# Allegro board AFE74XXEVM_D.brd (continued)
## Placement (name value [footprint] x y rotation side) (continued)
T3  NCR2-113+  [BALUN_6_NCR2]  35.74 62.33 270 bottom
T4  TCM2-672X+  [TFMR_6_160X150_50]  42.93 31.54 255 top
T5  TC1-1-43X+  [TFMR_5_150X150_50]  43.86 37.47 255 top
T6  TCM2-672X+  [TFMR_6_160X150_50]  48.45 30.06 255 top
T7  TC1-1-43X+  [TFMR_5_150X150_50]  49.38 35.99 255 top
T8  TCM2-672X+  [TFMR_6_160X150_50]  63.1 30.3 285 top
T9  TC1-1-43X+  [TFMR_5_150X150_50]  60.94 35.9 285 top
T10  TCM2-672X+  [TFMR_6_160X150_50]  68.62 31.78 285 top
T11  TC1-1-43X+  [TFMR_5_150X150_50]  66.46 37.38 285 top
T12  TCM2-672X+  [TFMR_6_160X150_50]  41.88 95.29 105 top
T13  TC1-1-43X+  [TFMR_5_150X150_50]  44.04 89.69 105 top
T14  TCM2-672X+  [TFMR_6_160X150_50]  47.4 96.77 105 top
T15  TC1-1-43X+  [TFMR_5_150X150_50]  49.56 91.17 105 top
T16  TCM2-672X+  [TFMR_6_160X150_50]  62.29 97 75 top
T17  TC1-1-43X+  [TFMR_5_150X150_50]  61.36 91.07 75 top
T18  TCM2-672X+  [TFMR_6_160X150_50]  67.81 95.52 75 top
T19  TC1-1-43X+  [TFMR_5_150X150_50]  66.88 89.59 75 top
T20  TCM3-452X-1+  [TFMR_6_160X150_50]  33.67 45.76 210 top
T21  TCM3-452X-1+  [TFMR_6_160X150_50]  29.79 57.1 180 top
T22  TCM3-452X-1+  [TFMR_6_160X150_50]  33.75 81.47 150 top
T23  TCM3-452X-1+  [TFMR_6_160X150_50]  29.79 69.81 180 top
T24  TC1-1-13M+  [TFMR_5_150X150_50]  99.16 104.39 270 bottom
TP1  Testloop_Red  [TESTPOINT_62DIA]  185.8 3.07 0 top
TP2  Testloop_Black  [TESTPOINT_62DIA]  180.82 3.02 0 top
TP3  TP_THVT_060_RND-WHT  [TP_THVT_060_RND]  214.91 32 0 top
TP4  TP_THVT_060_RND-WHT  [TP_THVT_060_RND]  201.24 94.95 0 top
TP5  TP_THVT_060_RND-WHT  [TP_THVT_060_RND]  198.96 88.29 0 top
U1  AFE76XX  [BGA_20X20_400_P8MM]  57.15 63.5 180 top
U2  NB7V33M  [QFN_16_124X124_PWRPAD]  92.15 104.52 0 bottom
U3  LMK04828  [QFN_64_360X360_0P50MM_PWRPAD]  102.34 90.86 90 bottom
U4  LP5907-3.3  [DBV5]  195.08 90.72 0 top
U5  FT4232H  [LQFP_64_402X402_20]  185.06 107.75 180 top
U6  TXS0108E  [QFN_20_183X144_RGY]  182.65 118.29 270 top
U7  TXS0108E  [QFN_20_183X144_RGY]  174.9 109.47 270 top
U8  93LC46B-I/MS  [MSOP_8_118X118_26]  187.5 96.9 270 top
U9  TXS0108E  [QFN_20_183X144_RGY]  174.78 102.49 270 top
U10  TXS0104E  [TSSOP14]  180.87 95.78 270 top
U11  TPS7A4700  [QFN20_RGW_P65PITCH]  178.1 30.02 270 top
U12  TPS2400  [DBV5]  185.72 17.5 0 top
U13  TPS62160  [SON_DSG_8]  92.2 8.69 0 top
U15  INA193  [DBV5]  82.04 13.49 0 top
U16  TPS56121  [SON_DQP_22_PWRPAD]  153.21 9.83 270 top
U17  INA195  [DBV5]  142.77 12.85 180 top
U18  TPS62480  [QFN16_RNC]  165.71 13.16 90 top
U19  INA193  [DBV5]  116.54 16.28 90 bottom
U20  TPS7A8300  [QFN20_RGW_P65PITCH]  116.74 10.74 0 top
U21  INA193  [DBV5]  89.23 21.59 0 bottom
U22  TPS7A8300  [QFN20_RGW_P65PITCH]  83.39 21.34 270 top
U23  TPS7A8300  [QFN20_RGW_P65PITCH]  119.08 23.77 0 top
U24  INA193  [DBV5]  119.13 29.31 90 bottom
U25  TPS7A8300  [QFN20_RGW_P65PITCH]  128.12 7.67 0 top
U26  INA193  [DBV5]  127.97 13.23 90 bottom
U27  TPS7A8300  [QFN20_RGW_P65PITCH]  147.96 27.76 0 top
U28  INA193  [DBV5]  147.75 33.2 90 bottom
U29  TPS7A8300  [QFN20_RGW_P65PITCH]  130.4 23.67 0 top
U30  INA193  [DBV5]  130.12 29.29 90 bottom
U31  24LC65  [SO_8_210X212_50]  191.47 22.07 90 top
U32  TPS7A4700  [QFN20_RGW_P65PITCH]  166.42 30.28 270 top
U33  TXS0104E  [TSSOP14]  175.01 94.23 90 top
Y1  122.88MHz  [VCXO_6_CUSTOM]  108.38 110.47 225 bottom
Y2  12MHz w/ 10pF  [XTAL_4_SM_130X102]  186.79 106.73 90 bottom

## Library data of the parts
C1 C4 C7 C132 C137 C148 C155 C228 C229 C253 C254 C256 C257 C278 C281 C288 C305 C306 C309 C313 C315 C317 C318 C358 C362 C377 C380 C390 C391 C399 C401 C408 C412 C419 C420 C434 C436 C440 C471 C479 C487 C495 = CAP NP_1: tolerance: 10%
C2 C3 C6 C9-C40 C64 C65 C80 C103 C106 C109 C113 C116 C119 C125 C126 C271 C282 C429-C431 C459-C461 C464 = CAP0402_0: tolerance: 10%
C41-C48 = CAP_0402_0.001uF_H
C49 C135 C139 C156 C161 C227 C231 C233-C239 C476 C484 C492 C500 = CAP_0402_0.01uF_H: tolerance: 10%
C50 C51 C61 C66 C67 C76 C78 C81 C82 C91 C93 C95-C97 C99 C101 C104 C107 C111 C114 C117 C122 C326 C332 C336 C349 C351 C357 C360 C364 C366 C368 C370 C375 C379 C383 C388 C395 C403 C411 C416 = CAP0201_0: tolerance: 20%
C52-C60 C63 C68-C75 C83-C90 C120 C121 C124 C183 C196 C203 C215 C353 C354 C372 C373 C385 C386 C396 C397 C405 C406 C414 C415 C441 C442 C457 C458 C463 = CAP0402_0: tolerance: 20%
C62 C77 C79 C92 C94 C98 C100 C102 C105 C108 C110 C112 C115 C118 C123 C311 C312 C361 C381 C392 C400 C409 C421 C433 C435 C462 C465 = CAP0201_0: tolerance: 10%
C127 C133 C140 C141 C149 C150 C157 C158 C469 C470 C477 C478 C485 C486 C493 C494 = CAP_0402_0.01uF_H
C129 C130 C142 C143 C151 C152 C159 C160 C472 C473 C480 C481 C488 C489 C496 C497 = CAP_0603_0.1uF_H
C131 C136 C144-C147 C153 C154 C474 C475 C482 C483 C490 C491 C498 C499 = CAP_0603_0.1uF_H: tolerance: .1pF
C184 C186-C189 C191 C194 C195 C198-C202 C205-C208 C210 C213 C214 C217-C221 C224 C240 C241 C247 C249 C250 C258-C267 C269 C270 C273-C277 C279 C284-C286 C292-C295 C297 C299 C300 C307 C308 C327 C329 C423-C428 C438 C439 C443 C444 C501 = CAPACITOR_NP_1: tolerance: 10%
C185 C197 C204 C216 = CAPACITOR_NP_1: tolerance: .05pF
C190 C192 C193 C209 C211 C212 = CAP_0603_0.1uF
C222 C223 C225 C245 C252 C280 C301 C314 C316 C321 C328 C341 C432 = CAP NP_0: tolerance: 10%
C226 = CAP NP_0: tolerance: 5%
C230 = CAP_0402_0.1uF: tolerance: 10%
C242 C244 C251 = CAP_0402_0.1uF_H: tolerance: 10%
C243 = CAP_0603_100pF_H
C246 C338 C340 C342 C347 = CAP_0402_2200pF_H
C248 = CAP_0402_10pF_H
C255 = CAPACITOR_NP_1: tolerance: 1%
C268 = CAP NP_2: tolerance: 20%
C272 C283 = CAP NP_0: tolerance: 20%
C287 C289 C330 C337 C447-C450 = CAP_1206
C290 C291 = CAP NP: tolerance: 10%
C296 C298 = CAP NP: tolerance: 5%
C302 C322 C323 C335 C343-C346 C445 C446 C468 = CAP_1210_22uF
C303 C304 C333 C334 C466 C467 = CAP POL
C310 C437 = CAP0603: tolerance: 10%
C325 C331 C348 C350 C352 C355 C356 C359 C363 C365 C367 C369 C371 C374 C376 C378 C382 C384 C387 C389 C393 C394 C398 C402 C404 C407 C410 C413 C417 C418 C451-C456 = CAP NP_1: tolerance: 20%
C422 = CAP NP_1
D1-D10 D14 = LED
D11 = LED_AMBER_1206
D12 = LED_GREEN_1206
D13 = DIODE SCHOTTKY
F1 = FUSE_0
FB1-FB11 = FERRITE_BEAD_0402_H
FB12 FB14 FB15 = FERRITE_BEAD
FB13 FB17 FB18 FB21-FB37 = BEAD_NFM31P
FB19 FB20 FB38 = FILTER_YFF31HC
HS1 = HEATSINK_1
J1 J3 J22-J25 = TMP_122841
J2 J4-J6 J27-J31 = SMP_PLUG_SMT
J7 = HEADER_3x18_100
J8 = HEADER_2x2_100
J9 = HEADER_3x21_100
J10 = HEADER_3x5_100
J11 = HEADER_2x5_100
J12 = HEADER_2x8_100
J13 = HEADER_3x8_100
J14-J21 J26 = SMA-END_PLUG_ROUND
J32 = CON_SMVT_40X10_ASP-134487-01
J33 = USB_MINI_AB_MNE20-5G5P10
J35 = CONN JACK PWR
J36 = HEADER_3x4_100
J37 = HEADER_1x4_100
J38 = HEADER 2/SM
JP1-JP8 = HDR_2x1_100
JP9 = HEADER 3
L1-L18 L27 L28 L33-L36 L41-L65 = CHOKE
L29 L31 L37 L39 = IND_0603_120nH_H
MT1-MT6 = MOUNTING_HOLE
PP1-PP32 = PROBE_POINT_0
Q1-Q23 Q26 Q27 = MMBT2222A
Q24 = CSD18532Q5B
Q25 = MOSFET_SiA517DJ
R1 R3 R4 R8 R10 R11 R14 R21 R40-R47 R50 R52 R54 R72 R74 R76 R93 R94 R96 R115 R118 R119 R202 R204-R206 R288 R330-R332 R335-R337 R340-R342 R345-R347 = Res_0603_Zero_H
R2 R7 R9 R166 = Res_0402_49.9
R5 R15 R16 R48 R58 R73 R77 R95 R97 R114 R116 R156 R158 R169 R172 R189 R191 R295 R296 R333 R334 R338 R339 R343 R344 R348 R349 = Res_0402_Zero_H_DNI
R6 R157 R302-R305 R309-R320 R322 R323 = Res_0402_49.9: tolerance: 1%
R12 R13 R32-R39 R138 R139 R142 R143 R146 R147 R150 R151 R196 R208-R210 R222-R224 R229 R234 R238 R246 R249 R251-R255 R257-R263 R265-R268 R270-R274 R276-R280 R282-R285 R297-R300 R321 = R: tolerance: 5%
R17 R20 R22-R25 R27-R29 R215-R219 R247 R248 R329 = R_0: tolerance: 1%
R18 R19 R26 R201 R203 R207 R214 R235-R237 R239 R240 R243-R245 R286 R287 R301 R308 R327 RS1-RS8 = R: tolerance: 1%
R30 R221 R306 R307 = Res_0402_1k
R31 R153 R160 R228 R232 R233 R241 R250 R256 R264 R269 R275 R281 R324-R326 R328 = R_1: tolerance: 1%
R136 R140 R144 R148 R211 R212 = Res_0402_10_H
R137 R141 R145 R149 R178 R184 = Res_0402_100_H
R152 = Res_0402_24.9
R154 R155 R162 R163 R167 R168 R173 R174 R176 R177 R182 R183 R187 R188 R190 R192-R194 R289-R294 = Res_0402_249
R159 = Res_0603_Zero_DNI
R161 = Res_0402_18
R164 R165 = Res_0402_270
R170 R171 R175 R179-R181 R185 R186 = RESISTOR_0: tolerance: 1%
R195 R197-R200 = RESISTOR_0
R213 R220 = RESISTOR
SHIELD1-SHIELD4 = 4T4R_TX_SHIELD
SHIELD5-SHIELD8 = 4T4R_RX_SHIELD
SJP1 = SMD_JUMPER_1x3
SW1 = SW PUSHBUTTON
T1 = TFMR_6_TCM2-43X+
T2 T3 = BALUN_NCR2-113+
T4 T6 T8 T10 T12 T14 T16 T18 = BALUN_TCM2-672X+
T5 T7 T9 T11 T13 T15 T17 T19 = BALUN_TC1-1-43X+
T20-T23 = TFMR_6_TCM3-452X+
T24 = TFMR_5_TC1-1-13MA+
TP1 TP2 = TESTLOOP_BLACK
TP3-TP5 = TP_THVT_060_RND-WHT
U1 = AFE768x
U2 = NB7V33M
U3 = LMK04828
U4 = LP5907
U5 = FT4232H_2
U6 U7 U9 = TXS0108E
U8 = EEPROM
U10 U33 = TXS0104E: Tolerance: ***; User Part Number: ***
U11 U32 = TPS7A4700
U12 = TPS2400
U13 = TPS6217x_SON8
U15 U17 U19 U21 U24 U26 U28 U30 = INA138
U16 = TPS56121
U18 = TPS62480/VQFN16
U20 U22 U23 U25 U27 U29 = TPS7A8300
U31 = 24LC65
Y1 = OSC_SM_6_TCO-2100-SERIES_2
Y2 = CRYSTAL1-4/SM

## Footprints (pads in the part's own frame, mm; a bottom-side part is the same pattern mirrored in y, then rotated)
4T4R_RX_SHIELD
  round 1.676 hole 1.168: MT1(0,-4.064) MT2(0,-9.144) MT3(13.335,-2.921) MT4(13.335,-11.811)
4T4R_TX_SHIELD
  round 1.676 hole 1.168: MT1(1.524,-8.89) MT2(4.318,0) MT3(8.128,-8.89)
0201
  rect 0.305x0.305 smd: 1(-0.305,0) 2(0.305,0)
0204
  rect 0.254x1.016 smd: 1(-0.254,0) 2(0.254,0)
0306
  rect 0.508x1.778 smd: 1(-0.483,0) 2(0.483,0)
0402
  rect 0.508x0.635 smd: 1(-0.508,0) 2(0.508,0)
0508
  rect 0.559x2.007 smd: 1(-0.593,0) 2(0.593,0)
0603
  rect 0.762x0.787 smd: 1(-0.787,0) 2(0.787,0)
0805
  rect 1.016x1.27 smd: 1(-1.016,0) 2(1.016,0)
01005
  rect 0.152x0.203 smd: 1(-0.18,0) 2(0.18,0)
1206
  rect 1.321x1.6 smd: 1(-1.524,0) 2(1.524,0)
1206_BEAD_NFM31P
  rect 1.016x1.575 smd: 1(-1.778,0) 3(1.778,0)
  rect 1.321x2.032 smd: 2(0,0)
1210
  rect 0.965x2.489 smd: 1(-1.372,0) 2(1.372,0)
2512
  rect 1.016x3.175 smd: 1(-3.1,0) 2(3.1,0)
7343
  rect 2.388x2.642 smd: 1(-3.404,0) 2(3.404,0)
BALUN_6_NCR2
  rect 0.356x0.762 smd: 1(-0.71,0.89) 2(0,0.89) 3(0.71,0.89) 4(0.71,-0.89) 5(0,-0.89) 6(-0.71,-0.89)
BGA_20X20_400_P8MM
  round 0.406 smd: A1(-7.6,7.6) A2(-6.8,7.6) A3(-6,7.6) A4(-5.2,7.6) A5(-4.4,7.6) A6(-3.6,7.6) A7(-2.8,7.6) A8(-2,7.6) A9(-1.2,7.6) A10(-0.4,7.6) A11(0.4,7.6) A12(1.2,7.6) A13(2,7.6) A14(2.8,7.6) A15(3.6,7.6) A16(4.4,7.6) A17(5.2,7.6) A18(6,7.6) A19(6.8,7.6) A20(7.6,7.6) B1(-7.6,6.8) B2(-6.8,6.8) B3(-6,6.8) B4(-5.2,6.8) B5(-4.4,6.8) B6(-3.6,6.8) B7(-2.8,6.8) B8(-2,6.8) B9(-1.2,6.8) B10(-0.4,6.8) B11(0.4,6.8) B12(1.2,6.8) B13(2,6.8) B14(2.8,6.8) B15(3.6,6.8) B16(4.4,6.8) B17(5.2,6.8) B18(6,6.8) B19(6.8,6.8) B20(7.6,6.8) C1(-7.6,6) C2(-6.8,6) C3(-6,6) C4(-5.2,6) C5(-4.4,6) C6(-3.6,6) C7(-2.8,6) C8(-2,6) C9(-1.2,6) C10(-0.4,6) C11(0.4,6) C12(1.2,6) C13(2,6) C14(2.8,6) C15(3.6,6) C16(4.4,6) C17(5.2,6) C18(6,6) C19(6.8,6) C20(7.6,6) D1(-7.6,5.2) D2(-6.8,5.2) D3(-6,5.2) D4(-5.2,5.2) D5(-4.4,5.2) D6(-3.6,5.2) D7(-2.8,5.2) D8(-2,5.2) D9(-1.2,5.2) D10(-0.4,5.2) D11(0.4,5.2) D12(1.2,5.2) D13(2,5.2) D14(2.8,5.2) D15(3.6,5.2) D16(4.4,5.2) D17(5.2,5.2) D18(6,5.2) D19(6.8,5.2) D20(7.6,5.2) E1(-7.6,4.4) E2(-6.8,4.4) E3(-6,4.4) E4(-5.2,4.4) E5(-4.4,4.4) E6(-3.6,4.4) E7(-2.8,4.4) E8(-2,4.4) E9(-1.2,4.4) E10(-0.4,4.4) E11(0.4,4.4) E12(1.2,4.4) E13(2,4.4) E14(2.8,4.4) E15(3.6,4.4) E16(4.4,4.4) E17(5.2,4.4) E18(6,4.4) E19(6.8,4.4) E20(7.6,4.4) F1(-7.6,3.6) F2(-6.8,3.6) F3(-6,3.6) F4(-5.2,3.6) F5(-4.4,3.6) F6(-3.6,3.6) F7(-2.8,3.6) F8(-2,3.6) F9(-1.2,3.6) F10(-0.4,3.6) F11(0.4,3.6) F12(1.2,3.6) F13(2,3.6) F14(2.8,3.6) F15(3.6,3.6) F16(4.4,3.6) F17(5.2,3.6) F18(6,3.6) F19(6.8,3.6) F20(7.6,3.6) G1(-7.6,2.8) G2(-6.8,2.8) G3(-6,2.8) G4(-5.2,2.8) G5(-4.4,2.8) G6(-3.6,2.8) G7(-2.8,2.8) G8(-2,2.8) G9(-1.2,2.8) G10(-0.4,2.8) G11(0.4,2.8) G12(1.2,2.8) G13(2,2.8) G14(2.8,2.8) G15(3.6,2.8) G16(4.4,2.8) G17(5.2,2.8) G18(6,2.8) G19(6.8,2.8) G20(7.6,2.8) H1(-7.6,2) H2(-6.8,2) H3(-6,2) H4(-5.2,2) H5(-4.4,2) H6(-3.6,2) H7(-2.8,2) H8(-2,2) H9(-1.2,2) H10(-0.4,2) H11(0.4,2) H12(1.2,2) H13(2,2) H14(2.8,2) H15(3.6,2) H16(4.4,2) H17(5.2,2) H18(6,2) H19(6.8,2) H20(7.6,2) J1(-7.6,1.2) J2(-6.8,1.2) J3(-6,1.2) J4(-5.2,1.2) J5(-4.4,1.2) J6(-3.6,1.2) J7(-2.8,1.2) J8(-2,1.2) J9(-1.2,1.2) J10(-0.4,1.2) J11(0.4,1.2) J12(1.2,1.2) J13(2,1.2) J14(2.8,1.2) J15(3.6,1.2) J16(4.4,1.2) J17(5.2,1.2) J18(6,1.2) J19(6.8,1.2) J20(7.6,1.2) K1(-7.6,0.4) K2(-6.8,0.4) K3(-6,0.4) K4(-5.2,0.4) K5(-4.4,0.4) K6(-3.6,0.4) K7(-2.8,0.4) K8(-2,0.4) K9(-1.2,0.4) K10(-0.4,0.4) K11(0.4,0.4) K12(1.2,0.4) K13(2,0.4) K14(2.8,0.4) K15(3.6,0.4) K16(4.4,0.4) K17(5.2,0.4) K18(6,0.4) K19(6.8,0.4) K20(7.6,0.4) L1(-7.6,-0.4) L2(-6.8,-0.4) L3(-6,-0.4) L4(-5.2,-0.4) L5(-4.4,-0.4) L6(-3.6,-0.4) L7(-2.8,-0.4) L8(-2,-0.4) L9(-1.2,-0.4) L10(-0.4,-0.4) L11(0.4,-0.4) L12(1.2,-0.4) L13(2,-0.4) L14(2.8,-0.4) L15(3.6,-0.4) L16(4.4,-0.4) L17(5.2,-0.4) L18(6,-0.4) L19(6.8,-0.4) L20(7.6,-0.4) M1(-7.6,-1.2) M2(-6.8,-1.2) M3(-6,-1.2) M4(-5.2,-1.2) M5(-4.4,-1.2) M6(-3.6,-1.2) M7(-2.8,-1.2) M8(-2,-1.2) M9(-1.2,-1.2) M10(-0.4,-1.2) M11(0.4,-1.2) M12(1.2,-1.2) M13(2,-1.2) M14(2.8,-1.2) M15(3.6,-1.2) M16(4.4,-1.2) M17(5.2,-1.2) M18(6,-1.2) M19(6.8,-1.2) M20(7.6,-1.2) N1(-7.6,-2) N2(-6.8,-2) N3(-6,-2) N4(-5.2,-2) N5(-4.4,-2) N6(-3.6,-2) N7(-2.8,-2) N8(-2,-2) N9(-1.2,-2) N10(-0.4,-2) N11(0.4,-2) N12(1.2,-2) N13(2,-2) N14(2.8,-2) N15(3.6,-2) N16(4.4,-2) N17(5.2,-2) N18(6,-2) N19(6.8,-2) N20(7.6,-2) P1(-7.6,-2.8) P2(-6.8,-2.8) P3(-6,-2.8) P4(-5.2,-2.8) P5(-4.4,-2.8) P6(-3.6,-2.8) P7(-2.8,-2.8) P8(-2,-2.8) P9(-1.2,-2.8) P10(-0.4,-2.8) P11(0.4,-2.8) P12(1.2,-2.8) P13(2,-2.8) P14(2.8,-2.8) P15(3.6,-2.8) P16(4.4,-2.8) P17(5.2,-2.8) P18(6,-2.8) P19(6.8,-2.8) P20(7.6,-2.8) R1(-7.6,-3.6) R2(-6.8,-3.6) R3(-6,-3.6) R4(-5.2,-3.6) R5(-4.4,-3.6) R6(-3.6,-3.6) R7(-2.8,-3.6) R8(-2,-3.6) R9(-1.2,-3.6) R10(-0.4,-3.6) R11(0.4,-3.6) R12(1.2,-3.6) R13(2,-3.6) R14(2.8,-3.6) R15(3.6,-3.6) R16(4.4,-3.6) R17(5.2,-3.6) R18(6,-3.6) R19(6.8,-3.6) R20(7.6,-3.6) T1(-7.6,-4.4) T2(-6.8,-4.4) T3(-6,-4.4) T4(-5.2,-4.4) T5(-4.4,-4.4) T6(-3.6,-4.4) T7(-2.8,-4.4) T8(-2,-4.4) T9(-1.2,-4.4) T10(-0.4,-4.4) T11(0.4,-4.4) T12(1.2,-4.4) T13(2,-4.4) T14(2.8,-4.4) T15(3.6,-4.4) T16(4.4,-4.4) T17(5.2,-4.4) T18(6,-4.4) T19(6.8,-4.4) T20(7.6,-4.4) U1(-7.6,-5.2) U2(-6.8,-5.2) U3(-6,-5.2) U4(-5.2,-5.2) U5(-4.4,-5.2) U6(-3.6,-5.2) U7(-2.8,-5.2) U8(-2,-5.2) U9(-1.2,-5.2) U10(-0.4,-5.2) U11(0.4,-5.2) U12(1.2,-5.2) U13(2,-5.2) U14(2.8,-5.2) U15(3.6,-5.2) U16(4.4,-5.2) U17(5.2,-5.2) U18(6,-5.2) U19(6.8,-5.2) U20(7.6,-5.2) V1(-7.6,-6) V2(-6.8,-6) V3(-6,-6) V4(-5.2,-6) V5(-4.4,-6) V6(-3.6,-6) V7(-2.8,-6) V8(-2,-6) V9(-1.2,-6) V10(-0.4,-6) V11(0.4,-6) V12(1.2,-6) V13(2,-6) V14(2.8,-6) V15(3.6,-6) V16(4.4,-6) V17(5.2,-6) V18(6,-6) V19(6.8,-6) V20(7.6,-6) W1(-7.6,-6.8) W2(-6.8,-6.8) W3(-6,-6.8) W4(-5.2,-6.8) W5(-4.4,-6.8) W6(-3.6,-6.8) W7(-2.8,-6.8) W8(-2,-6.8) W9(-1.2,-6.8) W10(-0.4,-6.8) W11(0.4,-6.8) W12(1.2,-6.8) W13(2,-6.8) W14(2.8,-6.8) W15(3.6,-6.8) W16(4.4,-6.8) W17(5.2,-6.8) W18(6,-6.8) W19(6.8,-6.8) W20(7.6,-6.8) Y1(-7.6,-7.6) Y2(-6.8,-7.6) Y3(-6,-7.6) Y4(-5.2,-7.6) Y5(-4.4,-7.6) Y6(-3.6,-7.6) Y7(-2.8,-7.6) Y8(-2,-7.6) Y9(-1.2,-7.6) Y10(-0.4,-7.6) Y11(0.4,-7.6) Y12(1.2,-7.6) Y13(2,-7.6) Y14(2.8,-7.6) Y15(3.6,-7.6) Y16(4.4,-7.6) Y17(5.2,-7.6) Y18(6,-7.6) Y19(6.8,-7.6) Y20(7.6,-7.6)
CON_RAPC722_JACK_THVT_3
  round 4.318 hole 3.556: 1(0,3.124)
  round 3.81 hole 3.048: 2(0,-3.124) 3(4.801,0.127)
CON_SMRT_USBMINI_AB_F_MOD
  round 0.025 hole 0.9 unplated: (1.4,2.2) (1.4,-2.2)
  rect 2.261x0.508 smd: 1(3.725,1.6) 2(3.725,0.8) 3(3.725,0) 4(3.725,-0.8) 5(3.725,-1.6)
  rect 3.988x2.057 smd: 6(-0.5,4.92) 9(-0.5,-4.93)
  rect 3.505x2.057 smd: 7(3.75,4.92) 8(3.75,-4.93)
CON_SMVT_40X10_SEAM_MTG
  round 3.81 hole 2.692: (-31.496,-2.007) (31.496,-2.007)
  round 1.27 hole 1.27 unplated: (-27.191,-3.048) (27.191,0)
  round 0.635 smd: A1(24.765,5.715) A2(23.495,5.715) A3(22.225,5.715) A4(20.955,5.715) A5(19.685,5.715) A6(18.415,5.715) A7(17.145,5.715) A8(15.875,5.715) A9(14.605,5.715) A10(13.335,5.715) A11(12.065,5.715) A12(10.795,5.715) A13(9.525,5.715) A14(8.255,5.715) A15(6.985,5.715) A16(5.715,5.715) A17(4.445,5.715) A18(3.175,5.715) A19(1.905,5.715) A20(0.635,5.715) A21(-0.635,5.715) A22(-1.905,5.715) A23(-3.175,5.715) A24(-4.445,5.715) A25(-5.715,5.715) A26(-6.985,5.715) A27(-8.255,5.715) A28(-9.525,5.715) A29(-10.795,5.715) A30(-12.065,5.715) A31(-13.335,5.715) A32(-14.605,5.715) A33(-15.875,5.715) A34(-17.145,5.715) A35(-18.415,5.715) A36(-19.685,5.715) A37(-20.955,5.715) A38(-22.225,5.715) A39(-23.495,5.715) A40(-24.765,5.715) B1(24.765,4.445) B2(23.495,4.445) B3(22.225,4.445) B4(20.955,4.445) B5(19.685,4.445) B6(18.415,4.445) B7(17.145,4.445) B8(15.875,4.445) B9(14.605,4.445) B10(13.335,4.445) B11(12.065,4.445) B12(10.795,4.445) B13(9.525,4.445) B14(8.255,4.445) B15(6.985,4.445) B16(5.715,4.445) B17(4.445,4.445) B18(3.175,4.445) B19(1.905,4.445) B20(0.635,4.445) B21(-0.635,4.445) B22(-1.905,4.445) B23(-3.175,4.445) B24(-4.445,4.445) B25(-5.715,4.445) B26(-6.985,4.445) B27(-8.255,4.445) B28(-9.525,4.445) B29(-10.795,4.445) B30(-12.065,4.445) B31(-13.335,4.445) B32(-14.605,4.445) B33(-15.875,4.445) B34(-17.145,4.445) B35(-18.415,4.445) B36(-19.685,4.445) B37(-20.955,4.445) B38(-22.225,4.445) B39(-23.495,4.445) B40(-24.765,4.445) C1(24.765,3.175) C2(23.495,3.175) C3(22.225,3.175) C4(20.955,3.175) C5(19.685,3.175) C6(18.415,3.175) C7(17.145,3.175) C8(15.875,3.175) C9(14.605,3.175) C10(13.335,3.175) C11(12.065,3.175) C12(10.795,3.175) C13(9.525,3.175) C14(8.255,3.175) C15(6.985,3.175) C16(5.715,3.175) C17(4.445,3.175) C18(3.175,3.175) C19(1.905,3.175) C20(0.635,3.175) C21(-0.635,3.175) C22(-1.905,3.175) C23(-3.175,3.175) C24(-4.445,3.175) C25(-5.715,3.175) C26(-6.985,3.175) C27(-8.255,3.175) C28(-9.525,3.175) C29(-10.795,3.175) C30(-12.065,3.175) C31(-13.335,3.175) C32(-14.605,3.175) C33(-15.875,3.175) C34(-17.145,3.175) C35(-18.415,3.175) C36(-19.685,3.175) C37(-20.955,3.175) C38(-22.225,3.175) C39(-23.495,3.175) C40(-24.765,3.175) D1(24.765,1.905) D2(23.495,1.905) D3(22.225,1.905) D4(20.955,1.905) D5(19.685,1.905) D6(18.415,1.905) D7(17.145,1.905) D8(15.875,1.905) D9(14.605,1.905) D10(13.335,1.905) D11(12.065,1.905) D12(10.795,1.905) D13(9.525,1.905) D14(8.255,1.905) D15(6.985,1.905) D16(5.715,1.905) D17(4.445,1.905) D18(3.175,1.905) D19(1.905,1.905) D20(0.635,1.905) D21(-0.635,1.905) D22(-1.905,1.905) D23(-3.175,1.905) D24(-4.445,1.905) D25(-5.715,1.905) D26(-6.985,1.905) D27(-8.255,1.905) D28(-9.525,1.905) D29(-10.795,1.905) D30(-12.065,1.905) D31(-13.335,1.905) D32(-14.605,1.905) D33(-15.875,1.905) D34(-17.145,1.905) D35(-18.415,1.905) D36(-19.685,1.905) D37(-20.955,1.905) D38(-22.225,1.905) D39(-23.495,1.905) D40(-24.765,1.905) E1(24.765,0.635) E2(23.495,0.635) E3(22.225,0.635) E4(20.955,0.635) E5(19.685,0.635) E6(18.415,0.635) E7(17.145,0.635) E8(15.875,0.635) E9(14.605,0.635) E10(13.335,0.635) E11(12.065,0.635) E12(10.795,0.635) E13(9.525,0.635) E14(8.255,0.635) E15(6.985,0.635) E16(5.715,0.635) E17(4.445,0.635) E18(3.175,0.635) E19(1.905,0.635) E20(0.635,0.635) E21(-0.635,0.635) E22(-1.905,0.635) E23(-3.175,0.635) E24(-4.445,0.635) E25(-5.715,0.635) E26(-6.985,0.635) E27(-8.255,0.635) E28(-9.525,0.635) E29(-10.795,0.635) E30(-12.065,0.635) E31(-13.335,0.635) E32(-14.605,0.635) E33(-15.875,0.635) E34(-17.145,0.635) E35(-18.415,0.635) E36(-19.685,0.635) E37(-20.955,0.635) E38(-22.225,0.635) E39(-23.495,0.635) E40(-24.765,0.635) F1(24.765,-0.635) F2(23.495,-0.635) F3(22.225,-0.635) F4(20.955,-0.635) F5(19.685,-0.635) F6(18.415,-0.635) F7(17.145,-0.635) F8(15.875,-0.635) F9(14.605,-0.635) F10(13.335,-0.635) F11(12.065,-0.635) F12(10.795,-0.635) F13(9.525,-0.635) F14(8.255,-0.635) F15(6.985,-0.635) F16(5.715,-0.635) F17(4.445,-0.635) F18(3.175,-0.635) F19(1.905,-0.635) F20(0.635,-0.635) F21(-0.635,-0.635) F22(-1.905,-0.635) F23(-3.175,-0.635) F24(-4.445,-0.635) F25(-5.715,-0.635) F26(-6.985,-0.635) F27(-8.255,-0.635) F28(-9.525,-0.635) F29(-10.795,-0.635) F30(-12.065,-0.635) F31(-13.335,-0.635) F32(-14.605,-0.635) F33(-15.875,-0.635) F34(-17.145,-0.635) F35(-18.415,-0.635) F36(-19.685,-0.635) F37(-20.955,-0.635) F38(-22.225,-0.635) F39(-23.495,-0.635) F40(-24.765,-0.635) G1(24.765,-1.905) G2(23.495,-1.905) G3(22.225,-1.905) G4(20.955,-1.905) G5(19.685,-1.905) G6(18.415,-1.905) G7(17.145,-1.905) G8(15.875,-1.905) G9(14.605,-1.905) G10(13.335,-1.905) G11(12.065,-1.905) G12(10.795,-1.905) G13(9.525,-1.905) G14(8.255,-1.905) G15(6.985,-1.905) G16(5.715,-1.905) G17(4.445,-1.905) G18(3.175,-1.905) G19(1.905,-1.905) G20(0.635,-1.905) G21(-0.635,-1.905) G22(-1.905,-1.905) G23(-3.175,-1.905) G24(-4.445,-1.905) G25(-5.715,-1.905) G26(-6.985,-1.905) G27(-8.255,-1.905) G28(-9.525,-1.905) G29(-10.795,-1.905) G30(-12.065,-1.905) G31(-13.335,-1.905) G32(-14.605,-1.905) G33(-15.875,-1.905) G34(-17.145,-1.905) G35(-18.415,-1.905) G36(-19.685,-1.905) G37(-20.955,-1.905) G38(-22.225,-1.905) G39(-23.495,-1.905) G40(-24.765,-1.905) H1(24.765,-3.175) H2(23.495,-3.175) H3(22.225,-3.175) H4(20.955,-3.175) H5(19.685,-3.175) H6(18.415,-3.175) H7(17.145,-3.175) H8(15.875,-3.175) H9(14.605,-3.175) H10(13.335,-3.175) H11(12.065,-3.175) H12(10.795,-3.175) H13(9.525,-3.175) H14(8.255,-3.175) H15(6.985,-3.175) H16(5.715,-3.175) H17(4.445,-3.175) H18(3.175,-3.175) H19(1.905,-3.175) H20(0.635,-3.175) H21(-0.635,-3.175) H22(-1.905,-3.175) H23(-3.175,-3.175) H24(-4.445,-3.175) H25(-5.715,-3.175) H26(-6.985,-3.175) H27(-8.255,-3.175) H28(-9.525,-3.175) H29(-10.795,-3.175) H30(-12.065,-3.175) H31(-13.335,-3.175) H32(-14.605,-3.175) H33(-15.875,-3.175) H34(-17.145,-3.175) H35(-18.415,-3.175) H36(-19.685,-3.175) H37(-20.955,-3.175) H38(-22.225,-3.175) H39(-23.495,-3.175) H40(-24.765,-3.175) J1(24.765,-4.445) J2(23.495,-4.445) J3(22.225,-4.445) J4(20.955,-4.445) J5(19.685,-4.445) J6(18.415,-4.445) J7(17.145,-4.445) J8(15.875,-4.445) J9(14.605,-4.445) J10(13.335,-4.445) J11(12.065,-4.445) J12(10.795,-4.445) J13(9.525,-4.445) J14(8.255,-4.445) J15(6.985,-4.445) J16(5.715,-4.445) J17(4.445,-4.445) J18(3.175,-4.445) J19(1.905,-4.445) J20(0.635,-4.445) J21(-0.635,-4.445) J22(-1.905,-4.445) J23(-3.175,-4.445) J24(-4.445,-4.445) J25(-5.715,-4.445) J26(-6.985,-4.445) J27(-8.255,-4.445) J28(-9.525,-4.445) J29(-10.795,-4.445) J30(-12.065,-4.445) J31(-13.335,-4.445) J32(-14.605,-4.445) J33(-15.875,-4.445) J34(-17.145,-4.445) J35(-18.415,-4.445) J36(-19.685,-4.445) J37(-20.955,-4.445) J38(-22.225,-4.445) J39(-23.495,-4.445) J40(-24.765,-4.445) K1(24.765,-5.715) K2(23.495,-5.715) K3(22.225,-5.715) K4(20.955,-5.715) K5(19.685,-5.715) K6(18.415,-5.715) K7(17.145,-5.715) K8(15.875,-5.715) K9(14.605,-5.715) K10(13.335,-5.715) K11(12.065,-5.715) K12(10.795,-5.715) K13(9.525,-5.715) K14(8.255,-5.715) K15(6.985,-5.715) K16(5.715,-5.715) K17(4.445,-5.715) K18(3.175,-5.715) K19(1.905,-5.715) K20(0.635,-5.715) K21(-0.635,-5.715) K22(-1.905,-5.715) K23(-3.175,-5.715) K24(-4.445,-5.715) K25(-5.715,-5.715) K26(-6.985,-5.715) K27(-8.255,-5.715) K28(-9.525,-5.715) K29(-10.795,-5.715) K30(-12.065,-5.715) K31(-13.335,-5.715) K32(-14.605,-5.715) K33(-15.875,-5.715) K34(-17.145,-5.715) K35(-18.415,-5.715) K36(-19.685,-5.715) K37(-20.955,-5.715) K38(-22.225,-5.715) K39(-23.495,-5.715) K40(-24.765,-5.715)
DBV5
  rect 1.4x0.5 smd: 1(-1.1,0.95) 2(-1.1,0) 3(-1.1,-0.95) 4(1.1,-0.95) 5(1.1,0.95)
DIODE_SM_DO_214AC
  rect 1.321x1.676 smd: 1(1.854,0) 2(-1.854,0)
FILTER_3_SM_YFF31HC
  rect 1.016x1.575 smd: 1(-1.778,0) 3(1.778,0)
  rect 1.397x2.413 smd: 2(0,0)
HDR_THVT_1X2_100_M
  rect 1.473x1.473 hole 0.965: 1(0,0)
  round 1.473 hole 0.965: 2(0,-2.54)
HDR_THVT_1X3_100_M
  rect 1.473x1.473 hole 0.965: 1(0,0)
  round 1.473 hole 0.965: 2(0,-2.54) 3(0,-5.08)
HDR_THVT_1X4_100_M
  rect 1.473x1.473 hole 0.965: 1(0,0)
  round 1.473 hole 0.965: 2(0,-2.54) 3(0,-5.08) 4(0,-7.62)
HDR_THVT_2X2_100_M
  rect 1.473x1.473 hole 0.965: 1(0,0)
  round 1.473 hole 0.965: 2(2.54,0) 3(0,-2.54) 4(2.54,-2.54)
HDR_THVT_2X5_100_M
  rect 1.473x1.473 hole 0.965: 1(0,0)
  round 1.473 hole 0.965: 2(2.54,0) 3(0,-2.54) 4(2.54,-2.54) 5(0,-5.08) 6(2.54,-5.08) 7(0,-7.62) 8(2.54,-7.62) 9(0,-10.16) 10(2.54,-10.16)
HDR_THVT_2X8_100_M
  rect 1.473x1.473 hole 0.965: 1(0,0)
  round 1.473 hole 0.965: 2(2.54,0) 3(0,-2.54) 4(2.54,-2.54) 5(0,-5.08) 6(2.54,-5.08) 7(0,-7.62) 8(2.54,-7.62) 9(0,-10.16) 10(2.54,-10.16) 11(0,-12.7) 12(2.54,-12.7) 13(0,-15.24) 14(2.54,-15.24) 15(0,-17.78) 16(2.54,-17.78)
HDR_THVT_3X4_100_M
  rect 1.473x1.473 hole 0.965: 1(0,0)
  round 1.473 hole 0.965: 2(2.54,0) 3(5.08,0) 4(0,-2.54) 5(2.54,-2.54) 6(5.08,-2.54) 7(0,-5.08) 8(2.54,-5.08) 9(5.08,-5.08) 10(0,-7.62) 11(2.54,-7.62) 12(5.08,-7.62)
HDR_THVT_3X5_100_M
  rect 1.473x1.473 hole 0.965: 1(0,0)
  round 1.473 hole 0.965: 2(2.54,0) 3(5.08,0) 4(0,-2.54) 5(2.54,-2.54) 6(5.08,-2.54) 7(0,-5.08) 8(2.54,-5.08) 9(5.08,-5.08) 10(0,-7.62) 11(2.54,-7.62) 12(5.08,-7.62) 13(0,-10.16) 14(2.54,-10.16) 15(5.08,-10.16)
HDR_THVT_3X8_100_M
  rect 1.473x1.473 hole 0.965: 1(0,0)
  round 1.473 hole 0.965: 2(2.54,0) 3(5.08,0) 4(0,-2.54) 5(2.54,-2.54) 6(5.08,-2.54) 7(0,-5.08) 8(2.54,-5.08) 9(5.08,-5.08) 10(0,-7.62) 11(2.54,-7.62) 12(5.08,-7.62) 13(0,-10.16) 14(2.54,-10.16) 15(5.08,-10.16) 16(0,-12.7) 17(2.54,-12.7) 18(5.08,-12.7) 19(0,-15.24) 20(2.54,-15.24) 21(5.08,-15.24) 22(0,-17.78) 23(2.54,-17.78) 24(5.08,-17.78)
HDR_THVT_3X18_100_M
  rect 1.473x1.473 hole 0.965: 1(-2.54,21.59)
  round 1.473 hole 0.965: 2(0,21.59) 3(2.54,21.59) 4(-2.54,19.05) 5(0,19.05) 6(2.54,19.05) 7(-2.54,16.51) 8(0,16.51) 9(2.54,16.51) 10(-2.54,13.97) 11(0,13.97) 12(2.54,13.97) 13(-2.54,11.43) 14(0,11.43) 15(2.54,11.43) 16(-2.54,8.89) 17(0,8.89) 18(2.54,8.89) 19(-2.54,6.35) 20(0,6.35) 21(2.54,6.35) 22(-2.54,3.81) 23(0,3.81) 24(2.54,3.81) 25(-2.54,1.27) 26(0,1.27) 27(2.54,1.27) 28(-2.54,-1.27) 29(0,-1.27) 30(2.54,-1.27) 31(-2.54,-3.81) 32(0,-3.81) 33(2.54,-3.81) 34(-2.54,-6.35) 35(0,-6.35) 36(2.54,-6.35) 37(-2.54,-8.89) 38(0,-8.89) 39(2.54,-8.89) 40(-2.54,-11.43) 41(0,-11.43) 42(2.54,-11.43) 43(-2.54,-13.97) 44(0,-13.97) 45(2.54,-13.97) 46(-2.54,-16.51) 47(0,-16.51) 48(2.54,-16.51) 49(-2.54,-19.05) 50(0,-19.05) 51(2.54,-19.05) 52(-2.54,-21.59) 53(0,-21.59) 54(2.54,-21.59)
HDR_THVT_3X21_100_M
  rect 1.473x1.473 hole 0.965: 1(-2.54,25.4)
  round 1.473 hole 0.965: 2(0,25.4) 3(2.54,25.4) 4(-2.54,22.86) 5(0,22.86) 6(2.54,22.86) 7(-2.54,20.32) 8(0,20.32) 9(2.54,20.32) 10(-2.54,17.78) 11(0,17.78) 12(2.54,17.78) 13(-2.54,15.24) 14(0,15.24) 15(2.54,15.24) 16(-2.54,12.7) 17(0,12.7) 18(2.54,12.7) 19(-2.54,10.16) 20(0,10.16) 21(2.54,10.16) 22(-2.54,7.62) 23(0,7.62) 24(2.54,7.62) 25(-2.54,5.08) 26(0,5.08) 27(2.54,5.08) 28(-2.54,2.54) 29(0,2.54) 30(2.54,2.54) 31(-2.54,0) 32(0,0) 33(2.54,0) 34(-2.54,-2.54) 35(0,-2.54) 36(2.54,-2.54) 37(-2.54,-5.08) 38(0,-5.08) 39(2.54,-5.08) 40(-2.54,-7.62) 41(0,-7.62) 42(2.54,-7.62) 43(-2.54,-10.16) 44(0,-10.16) 45(2.54,-10.16) 46(-2.54,-12.7) 47(0,-12.7) 48(2.54,-12.7) 49(-2.54,-15.24) 50(0,-15.24) 51(2.54,-15.24) 52(-2.54,-17.78) 53(0,-17.78) 54(2.54,-17.78) 55(-2.54,-20.32) 56(0,-20.32) 57(2.54,-20.32) 58(-2.54,-22.86) 59(0,-22.86) 60(2.54,-22.86) 61(-2.54,-25.4) 62(0,-25.4) 63(2.54,-25.4)
HEATSINK_27X27MM_ATS
  round 5.715 hole 3.175: MTG1(-10.5,-10.5) MTG2(10.5,10.5)
IND_0603
  rect 0.635x1.016 smd: 1(-0.635,0) 2(0.635,0)
IND_0806
  rect 0.559x1.626 smd: 1(-0.7,0) 2(0.7,0)
IND_SM_3020
  rect 1.295x3.404 smd: 1(-1.041,0) 2(1.041,0)
IND_SM_XAL60XX
  rect 1.422x5.486 smd: 1(-2.032,0) 2(2.032,0)
IND_SM_XFL4015
  rect 1.2x3.5 smd: 1(-1.225,0) 2(1.225,0)
LED_0603
  rect 0.762x0.813 smd: 1(-0.787,0) 2(0.787,0)
LED_1206
  rect 1.27x1.6 smd: 1(-1.524,0) 2(1.524,0)
LQFP_64_402X402_20
  round 1.016 smd: (-6.35,6.35) (6.35,-6.35)
  rect 2.032x0.33 smd: 1(-5.625,3.75) 2(-5.625,3.25) 3(-5.625,2.75) 4(-5.625,2.25) 5(-5.625,1.75) 6(-5.625,1.25) 7(-5.625,0.75) 8(-5.625,0.25) 9(-5.625,-0.25) 10(-5.625,-0.75) 11(-5.625,-1.25) 12(-5.625,-1.75) 13(-5.625,-2.25) 14(-5.625,-2.75) 15(-5.625,-3.25) 16(-5.625,-3.75) 33(5.625,-3.75) 34(5.625,-3.25) 35(5.625,-2.75) 36(5.625,-2.25) 37(5.625,-1.75) 38(5.625,-1.25) 39(5.625,-0.75) 40(5.625,-0.25) 41(5.625,0.25) 42(5.625,0.75) 43(5.625,1.25) 44(5.625,1.75) 45(5.625,2.25) 46(5.625,2.75) 47(5.625,3.25) 48(5.625,3.75)
  rect 0.33x2.032 smd: 17(-3.75,-5.625) 18(-3.25,-5.625) 19(-2.75,-5.625) 20(-2.25,-5.625) 21(-1.75,-5.625) 22(-1.25,-5.625) 23(-0.75,-5.625) 24(-0.25,-5.625) 25(0.25,-5.625) 26(0.75,-5.625) 27(1.25,-5.625) 28(1.75,-5.625) 29(2.25,-5.625) 30(2.75,-5.625) 31(3.25,-5.625) 32(3.75,-5.625) 49(3.75,5.625) 50(3.25,5.625) 51(2.75,5.625) 52(2.25,5.625) 53(1.75,5.625) 54(1.25,5.625) 55(0.75,5.625) 56(0.25,5.625) 57(-0.25,5.625) 58(-0.75,5.625) 59(-1.25,5.625) 60(-1.75,5.625) 61(-2.25,5.625) 62(-2.75,5.625) 63(-3.25,5.625) 64(-3.75,5.625)
MFG125_PLATED
  round 3.556 hole 3.175: 1(0,0)
MSOP_8_118X118_26
  rect 1.575x0.406 smd: 1(-2.225,0.975) 2(-2.225,0.325) 3(-2.225,-0.325) 4(-2.225,-0.975) 5(2.225,-0.975) 6(2.225,-0.325) 7(2.225,0.325) 8(2.225,0.975)
PROBE_POINT_22PAD
  round 0.508 smd: 1(0,0)
QFN16_RNC
  rect 1.321x0.254 smd: 1(-0.8,0.525) 2(-0.8,0) 3(-0.8,-0.525) 9(0.8,-0.525) 10(0.8,0) 11(0.8,0.525)
  rect 0.254x0.61 smd: 4(-1,-1.4) 5(-0.5,-1.4) 6(0,-1.4) 7(0.5,-1.4) 8(1,-1.4) 12(1,1.4) 13(0.5,1.4) 14(0,1.4) 15(-0.5,1.4) 16(-1,1.4)
QFN20_RGW_P65PITCH
  custom 0.09x0.09 smd: 1(-2.607,1.3) 2(-2.607,0.65) 3(-2.607,0) 4(-2.607,-0.65) 5(-2.607,-1.3) 6(-1.3,-2.607) 7(-0.65,-2.607) 8(0,-2.607) 9(0.65,-2.607) 10(1.3,-2.607) 11(2.607,-1.3) 12(2.607,-0.65) 13(2.607,0) 14(2.607,0.65) 15(2.607,1.3) 16(1.3,2.607) 17(0.65,2.607) 18(0,2.607) 19(-0.65,2.607) 20(-1.3,2.607)
  rect 3.302x3.302 smd: 21(0,0)
QFN_16_124X124_PWRPAD
  rect 0.889x0.305 smd: 1(-1.6,0.749) 2(-1.6,0.249) 3(-1.6,-0.249) 4(-1.6,-0.749) 9(1.6,-0.749) 10(1.6,-0.249) 11(1.6,0.249) 12(1.6,0.749)
  rect 0.305x0.889 smd: 5(-0.749,-1.6) 6(-0.249,-1.6) 7(0.249,-1.6) 8(0.749,-1.6) 13(0.749,1.6) 14(0.249,1.6) 15(-0.249,1.6) 16(-0.749,1.6)
  rect 1.651x1.651 smd: 17(0,0)
QFN_20_183X144_RGY
  rect 0.762x0.356 smd: 1(-2.125,-0.75) 10(2.125,-0.75) 11(2.125,0.75) 20(-2.125,0.75)
  rect 0.356x0.762 smd: 2(-1.75,-1.625) 3(-1.25,-1.625) 4(-0.75,-1.625) 5(-0.25,-1.625) 6(0.25,-1.625) 7(0.75,-1.625) 8(1.25,-1.625) 9(1.75,-1.625) 12(1.75,1.625) 13(1.25,1.625) 14(0.75,1.625) 15(0.25,1.625) 16(-0.25,1.625) 17(-0.75,1.625) 18(-1.25,1.625) 19(-1.75,1.625)
  rect 3.15x2.159 smd: 21(0,0)
QFN_64_360X360_0P50MM_PWRPAD
  oval 1.016x0.305 smd: 1(-4.58,3.753) 2(-4.58,3.252) 3(-4.58,2.752) 4(-4.58,2.252) 5(-4.58,1.751) 6(-4.58,1.251) 7(-4.58,0.751) 8(-4.58,0.25) 9(-4.58,-0.25) 10(-4.58,-0.751) 11(-4.58,-1.251) 12(-4.58,-1.751) 13(-4.58,-2.252) 14(-4.58,-2.752) 15(-4.58,-3.252) 16(-4.58,-3.753) 33(4.58,-3.753) 34(4.58,-3.252) 35(4.58,-2.752) 36(4.58,-2.252) 37(4.58,-1.751) 38(4.58,-1.251) 39(4.58,-0.751) 40(4.58,-0.25) 41(4.58,0.25) 42(4.58,0.751) 43(4.58,1.251) 44(4.58,1.751) 45(4.58,2.252) 46(4.58,2.752) 47(4.58,3.252) 48(4.58,3.753)
  oval 0.305x1.016 smd: 17(-3.753,-4.58) 18(-3.252,-4.58) 19(-2.752,-4.58) 20(-2.252,-4.58) 21(-1.751,-4.58) 22(-1.251,-4.58) 23(-0.751,-4.58) 24(-0.25,-4.58) 25(0.25,-4.58) 26(0.751,-4.58) 27(1.251,-4.58) 28(1.751,-4.58) 29(2.252,-4.58) 30(2.752,-4.58) 31(3.252,-4.58) 32(3.753,-4.58) 49(3.753,4.58) 50(3.252,4.58) 51(2.752,4.58) 52(2.252,4.58) 53(1.751,4.58) 54(1.251,4.58) 55(0.751,4.58) 56(0.25,4.58) 57(-0.25,4.58) 58(-0.751,4.58) 59(-1.251,4.58) 60(-1.751,4.58) 61(-2.252,4.58) 62(-2.752,4.58) 63(-3.252,4.58) 64(-3.753,4.58)
  rect 7.366x7.366 smd: 65(0,0)
SC70-6L_85X85
  rect 0.356x0.33 smd: 1(-0.65,-0.93) 2(0,-0.93) 3(0.65,-0.93) 4(0.65,0.93) 5(0,0.93) 6(-0.65,0.93)
  rect 0.61x0.94 smd: D1(-0.467,0) D2(0.467,0)
SMA_SMEL_DUAL_PSF-S01_250X215
  rect 0.508x4.064 smd: 1(0,-2.032)
  rect 3.048x4.064 smd: 2(-3.556,-2.032) 3(3.556,-2.032) 4(-3.556,-2.032) 5(3.556,-2.032)
SMD_JUMPER_L_0402
  rect 0.508x0.508 smd: 1(-0.508,0) 2(0.508,0) 3(0.508,1.016)
SMP_B120
  rect 0.508x1.321 smd: 1(0,-3.1)
  custom 1.3x1.3 smd: 2(0,0)
SO_8_210X212_50
  rect 0.508x1.778 smd: 1(-1.905,-3.594) 2(-0.635,-3.594) 3(0.635,-3.594) 4(1.905,-3.594) 5(1.905,3.594) 6(0.635,3.594) 7(-0.635,3.594) 8(-1.905,3.594)
SON_DQP_22_PWRPAD
  rect 1.016x0.305 smd: 1(-2.25,2.5) 2(-2.25,2) 3(-2.25,1.5) 4(-2.25,1) 5(-2.25,0.5) 6(-2.25,0) 7(-2.25,-0.5) 8(-2.25,-1) 9(-2.25,-1.5) 10(-2.25,-2) 11(-2.25,-2.5) 12(2.25,-2.5) 13(2.25,-2) 14(2.25,-1.5) 15(2.25,-1) 16(2.25,-0.5) 17(2.25,0) 18(2.25,0.5) 19(2.25,1) 20(2.25,1.5) 21(2.25,2) 22(2.25,2.5)
  rect 2.54x5.08 smd: 23(0,0)
SON_DSG_8
  rect 0.508x0.33 smd: 1(-0.903,0.75) 2(-0.903,0.25) 3(-0.903,-0.25) 4(-0.903,-0.75) 5(0.903,-0.75) 6(0.903,-0.25) 7(0.903,0.25) 8(0.903,0.75)
  rect 0.762x1.778 smd: 9(0,0)
SON_Q5B_8
  rect 1.372x0.711 smd: 1(-2.767,1.905) 2(-2.767,0.635) 3(-2.767,-0.635) 4(-2.767,-1.905) 5(2.767,-1.905) 6(2.767,-0.635) 7(2.767,0.635) 8(2.767,1.905)
SOT_416_3_63X31
  rect 0.508x0.356 smd: 1(0,-0.152) 2(0,-1.168) 3(1.295,-0.66)
SW_THVT_SPST_PTS635SL43
  round 2.159 hole 1.397: 1(-3.251,0) 2(3.251,0)
TESTPOINT_62DIA
  round 2.337 hole 1.575: 1(0,0)
TFMR_5_150X150_50
  rect 1.651x0.762 smd: 1(1.587,1.27) 2(1.587,0) 3(1.587,-1.27) 4(-1.587,-1.27) 6(-1.587,1.27)
TFMR_6_160X150_50
  rect 1.651x0.762 smd: 1(1.587,1.27) 2(1.587,0) 3(1.587,-1.27) 4(-1.587,-1.27) 5(-1.587,0) 6(-1.587,1.27)
TP_THVT_060_RND
  round 1.575 hole 1.016: 1(0,0)
TSSOP14
  rect 1.651x0.33 smd: 1(-2.87,1.956) 2(-2.87,1.306) 3(-2.87,0.655) 4(-2.87,0.005) 5(-2.87,-0.645) 6(-2.87,-1.295) 7(-2.87,-1.946) 8(2.87,-1.946) 9(2.87,-1.295) 10(2.87,-0.645) 11(2.87,0.005) 12(2.87,0.655) 13(2.87,1.306) 14(2.87,1.956)
VCXO_6_CUSTOM
  rect 5.74x1.956 smd: 1(-3.81,2.54) 2(-3.81,0) 3(-3.81,-2.54) 4(3.81,-2.54) 5(3.81,0) 6(3.81,2.54)
XTAL_4_SM_130X102
  rect 1.4x1.2 smd: 1(-1.1,-0.85) 2(1.1,-0.85) 3(1.1,0.85) 4(-1.1,0.85)

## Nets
1.8V_USB: C273.2 C275.2 C279.2 C286.2 C288.1 C289.1 C293.2 C295.2 C299.2 C444.2 U5.12(VCORE#12) U5.37(VCORE#37) U5.49(VREGOUT) U5.64(VCORE#64) U6.2(VCCA) U6.10(OE) U7.2(VCCA) U7.10(OE) U9.2(VCCA) U9.10(OE) U10.1(VCCA) U10.8(OE) U33.1(VCCA) U33.8(OE)
3.3V_USB: C274.2 C276.2 C277.2 C284.2 C285.1 C287.1 C292.1 C294.1 C297.2 C300.1 C443.1 FB12.1 FB13.3 FB14.1 R217.2 R218.2 R219.2 U5.20(VCCIO#20) U5.31(VCCIO#31) U5.42(VCCIO#42) U5.50(VREGIN) U5.56(VCCIO#56) U6.19(VCCB) U7.19(VCCB) U8.6(ORG) U8.8(VCC) U9.19(VCCB) U10.14(VCCB) U33.14(VCCB)
5.0V_SOURCE: F1.1 J35.1 Q24.5(D5) Q24.6(D6) Q24.7(D7) Q24.8(D8) TP1.1(TP) U12.5(VIN)
5VUSB: R210.1 R213.1
12VFMC: J32.C35 J32.C37 PP29.1
+1.0V_ANALOG_SENSE: C358.2 FB21.1 FB22.1 FB24.1 FB26.1 FB28.1 FB30.1 RS3.1 U19.4(VIN-) U20.2(SNS)
+1.0V_SENSE: C408.2 FB34.1 FB35.1 RS7.1 U27.2(SNS) U28.4(VIN-)
+1.2V_RX_PWR_SENSE: C390.2 FB32.1 RS5.1 U23.2(SNS) U24.4(VIN-)
+1.5V_SENSE: C419.2 FB36.1 RS8.1 U29.2(SNS) U30.4(VIN-)
+1.8V_ANALOG_SENSE: C377.2 FB23.1 FB25.1 FB27.1 FB29.3 FB31.1 RS4.1 U21.4(VIN-) U22.2(SNS)
+1.8V_RX_PWR_SENSE: C399.2 FB33.1 RS6.1 U25.2(SNS) U26.4(VIN-)
+2.2V: C345.2 C346.2 C352.1 C354.1 C371.1 C372.1 C384.1 C385.1 C393.1 C396.1 C404.1 C405.1 C413.1 C414.1 C445.2 C446.2 L47.2 L48.2 R247.1 R308.1 R324.2 R325.2 R326.2 R327.1 R328.2 U18.16(VO) U20.15(IN1) U20.16(IN2) U20.17(IN3) U22.15(IN1) U22.16(IN2) U22.17(IN3) U23.15(IN1) U23.16(IN2) U23.17(IN3) U25.15(IN1) U25.16(IN2) U25.17(IN3) U27.15(IN1) U27.16(IN2) U27.17(IN3) U29.15(IN1) U29.16(IN2) U29.17(IN3)
+2.5VCLK: C233.1 C234.1 C235.1 C236.1 C237.1 C433.1 C434.1 FB37.3 PP32.1 R170.1 R171.1 U2.9(VCC#9) U2.12(VCC#12) U2.13(VCC#13) U2.14(VCC#14) U2.16(VCC#16) U32.3(SENSE)
+3.3VCLK: C312.1 C313.1 FB1.2 FB2.1 FB3.1 FB4.1 FB5.1 FB6.1 FB10.1 FB11.1 FB17.3 PP1.1 R152.1 R175.1 R181.1 SJP1.3(PIN3) U11.3(SENSE)
+5VIN: C278.1 C301.1 C302.2 C303.1 C304.1 C305.1 C306.1 C307.2 C308.2 C315.1 C317.1 C343.2 C344.2 C438.2 C439.2 C440.1 C466.1 C467.1 C468.2 D1.1(ANODE) D2.1(ANODE) D3.1(ANODE) D8.1(ANODE) D9.1(ANODE) D10.1(ANODE) F1.2 J38.1 JP9.1(PIN1) L49.1 Q24.1(S1) Q24.2(S2) Q24.3(S3) Q25.4(S2) R208.2 R221.1 R246.2 R306.2 R329.1 U4.1(VIN) U11.13(EN) U11.15(IN2) U11.16(IN1) U13.2(VIN) U15.5(V+) U17.5(V+) U18.3(IN1) U18.8(MODE) U18.9(IN2) U19.5(V+) U21.5(V+) U24.5(V+) U26.5(V+) U28.5(V+) U30.5(V+) U32.15(IN2) U32.16(IN1)
-1.8V: C317.2 C321.1 C322.1 C323.1 D13.1(ANODE) R233.1 R307.2 RS1.2 U13.1(PGND) U13.4(AGND) U13.9(PWRPAD) U15.4(VIN-)
DVDD: C50.1 C51.1 C52.1 C53.1 C54.1 C55.1 C56.1 C57.1 C58.1 C59.1 C60.1 C120.1 C121.1 C331.1 C332.1 FB20.3 FB38.3 PP5.1 R301.1 U1.G13(DVDD#G13) U1.H6(DVDD#H6) U1.H7(DVDD#H7) U1.H13(DVDD#H13) U1.J12(DVDD#J12) U1.J13(DVDD#J13) U1.K6(DVDDPR#K6) U1.K7(DVDDPR#K7) U1.K8(DVDDAR) U1.K9(DVDD#K9) U1.K10(VPP) U1.K11(DVDD#K11) U1.K12(DVDD#K12) U1.K13(DVDD#K13) U1.L6(DVDD#L6) U1.L7(VNWA) U1.L8(DVDD#L8) U1.L9(DVDD#L9) U1.L10(DVDD#L10) U1.L11(DVDD#L11) U1.L12(DVDD#L12) U1.L13(DVDD#L13) U1.M12(DVDD#M12) U1.M13(DVDD#M13) U1.N6(DVDD#N6) U1.N7(DVDD#N7) U1.N13(DVDD#N13) U1.P13(DVDD#P13)
GND: C41.2 C49.2 C50.2 C51.2 C52.2 C53.2 C54.2 C55.2 C56.2 C57.2 C58.2 C59.2 C60.2 C61.2 C62.2 C63.2 C64.2 C65.2 C66.2 C67.2 C68.2 C69.2 C70.2 C71.2 C72.2 C73.2 C74.2 C75.2 C76.2 C77.2 C78.2 C79.2 C80.2 C81.2 C82.2 C83.2 C84.2 C85.2 C86.2 C87.2 C88.2 C89.2 C90.2 C91.2 C92.2 C93.2 C94.2 C95.2 C96.2 C97.2 C98.2 C99.2 C100.2 C101.2 C102.2 C103.2 C104.2 C105.2 C106.2 C107.2 C108.2 C109.2 C110.2 C111.2 C112.2 C113.2 C114.2 C115.2 C116.2 C117.2 C118.2 C119.2 C120.2 C121.2 C122.2 C123.2 C124.2 C125.2 C126.2 C135.1 C139.1 C156.1 C161.1 C183.2 C185.1 C186.2 C188.1 C189.1 C190.2 C191.2 C192.2 C193.2 C194.2 C196.2 C197.1 C198.1 C200.1 C201.1 C203.2 C204.1 C205.1 C207.1 C208.1 C209.2 C210.2 C211.2 C212.2 C213.2 C215.2 C216.1 C217.1 C219.1 C220.1 C223.2 C226.2 C230.1 C233.2 C234.2 C235.2 C236.2 C237.2 C242.1 C243.1 C246.1 C247.1 C248.1 C255.1 C258.1 C259.1 C260.1 C261.1 C262.1 C263.1 C264.1 C265.1 C266.1 C267.2 C268.2 C269.1 C270.1 C271.2 C272.2 C273.1 C274.1 C275.1 C276.1 C277.1 C278.2 C279.1 C280.2 C281.2 C282.2 C283.2 C284.1 C285.2 C286.1 C287.2 C288.2 C289.2 C290.2 C291.2 C292.2 C293.1 C294.2 C295.1 C296.2 C297.1 C298.2 C299.1 C300.2 C301.2 C302.1 C303.2 C304.2 C305.2 C306.2 C307.1 C308.1 C309.2 C310.2 C311.2 C312.2 C313.2 C314.2 C315.2 C316.2 C318.2 C321.2 C322.2 C323.2 C325.2 C326.2 C328.2 C329.1 C330.2 C331.2 C332.2 C333.2 C334.2 C335.1 C336.2 C337.2 C341.2 C343.1 C344.1 C345.1 C346.1 C347.2 C348.2 C349.2 C350.2 C351.2 C352.2 C353.2 C354.2 C355.2 C356.2 C357.2 C359.2 C360.2 C361.2 C362.2 C363.2 C364.2 C365.2 C366.2 C367.2 C368.2 C369.2 C370.2 C371.2 C372.2 C373.2 C374.2 C375.2 C376.2 C378.2 C379.2 C380.2 C381.2 C382.2 C383.2 C384.2 C385.2 C386.2 C387.2 C388.2 C389.2 C391.2 C392.2 C393.2 C394.2 C395.2 C396.2 C397.2 C398.2 C400.2 C401.2 C402.2 C403.2 C404.2 C405.2 C406.2 C407.2 C409.2 C410.2 C411.2 C412.2 C413.2 C414.2 C415.2 C416.2 C417.2 C418.2 C420.2 C421.2 C422.1 C429.2 C430.2 C431.2 C432.2 C433.2 C434.2 C435.2 C436.2 C437.2 C438.1 C439.1 C440.2 C441.2 C442.2 C443.2 C444.1 C445.1 C446.1 C447.2 C448.2 C449.2 C450.2 C451.2 C452.2 C453.2 C454.2 C455.2 C456.2 C457.2 C458.2 C459.2 C460.2 C461.2 C462.2 C463.2 C464.2 C465.2 C466.2 C467.2 C468.1 C476.1 C484.1 C492.1 C500.1 C501.2 D4.2(CATHODE) D5.2(CATHODE) D6.2(CATHODE) D7.2(CATHODE) D11.2(CATHODE) D12.2(CATHODE) D13.2(CATHODE) D14.2(CATHODE) FB13.2 FB17.2 FB18.2 FB19.2 FB20.2 FB21.2 FB22.2 FB23.2 FB24.2 FB25.2 FB26.2 FB27.2 FB28.2 FB29.2 FB30.2 FB31.2 FB32.2 FB33.2 FB34.2 FB35.2 FB36.2 FB37.2 FB38.2 HS1.MTG1 HS1.MTG2 J1.2(GND#2) J1.3(GND#3) J1.4(GND#4) J1.5(GND#5) J2.2(SHIELD1) J3.2(GND#2) J3.3(GND#3) J3.4(GND#4) J3.5(GND#5) J4.2(SHIELD1) J5.2(SHIELD1) J6.2(SHIELD1) J9.55 J9.58 J9.61 J11.2 J11.4 J11.6 J11.8 J11.10 J14.2(SHIELD2) J14.3(SHIELD3) J14.4(SHIELD4) J14.5(SHIELD1) J15.2(SHIELD2) J15.3(SHIELD3) J15.4(SHIELD4) J15.5(SHIELD1) J16.2(SHIELD2) J16.3(SHIELD3) J16.4(SHIELD4) J16.5(SHIELD1) J17.2(SHIELD2) J17.3(SHIELD3) J17.4(SHIELD4) J17.5(SHIELD1) J18.2(SHIELD2) J18.3(SHIELD3) J18.4(SHIELD4) J18.5(SHIELD1) J19.2(SHIELD2) J19.3(SHIELD3) J19.4(SHIELD4) J19.5(SHIELD1) J20.2(SHIELD2) J20.3(SHIELD3) J20.4(SHIELD4) J20.5(SHIELD1) J21.2(SHIELD2) J21.3(SHIELD3) J21.4(SHIELD4) J21.5(SHIELD1) J22.2(GND#2) J22.3(GND#3) J22.4(GND#4) J22.5(GND#5) J23.2(GND#2) J23.3(GND#3) J23.4(GND#4) J23.5(GND#5) J24.2(GND#2) J24.3(GND#3) J24.4(GND#4) J24.5(GND#5) J25.2(GND#2) J25.3(GND#3) J25.4(GND#4) J25.5(GND#5) J26.2(SHIELD2) J26.3(SHIELD3) J26.4(SHIELD4) J26.5(SHIELD1) J27.2(SHIELD1) J28.2(SHIELD1) J29.2(SHIELD1) J30.2(SHIELD1) J31.2(SHIELD1) J32.A1 J32.A4 J32.A5 J32.A8 J32.A9 J32.A12 J32.A13 J32.A16 J32.A17 J32.A20 J32.A21 J32.A24 J32.A25 J32.A28 J32.A29 J32.A32 J32.A33 J32.A36 J32.A37 J32.A40 J32.B2 J32.B3 J32.B6 J32.B7 J32.B10 J32.B11 J32.B14 J32.B15 J32.B18 J32.B19 J32.B22 J32.B23 J32.B26 J32.B27 J32.B30 J32.B31 J32.B34 J32.B35 J32.B38 J32.B39 J32.C1 J32.C4 J32.C5 J32.C8 J32.C9 J32.C12 J32.C13 J32.C16 J32.C17 J32.C20 J32.C21 J32.C24 J32.C25 J32.C28 J32.C29 J32.C32 J32.C33 J32.C36 J32.C38 J32.C40 J32.D2 J32.D3 J32.D6 J32.D7 J32.D10 J32.D13 J32.D16 J32.D19 J32.D22 J32.D25 J32.D28 J32.D37 J32.D39 J32.E1 J32.E4 J32.E5 J32.E8 J32.E11 J32.E14 J32.E17 J32.E20 J32.E23 J32.E26 J32.E29 J32.E32 J32.E35 J32.E38 J32.E40 J32.F3 J32.F6 J32.F9 J32.F12 J32.F15 J32.F18 J32.F21 J32.F24 J32.F27 J32.F30 J32.F33 J32.F36 J32.F39 J32.G1 J32.G4 J32.G5 J32.G8 J32.G11 J32.G14 J32.G17 J32.G20 J32.G23 J32.G26 J32.G29 J32.G32 J32.G35 J32.G38 J32.G40 J32.H3 J32.H6 J32.H9 J32.H12 J32.H15 J32.H18 J32.H21 J32.H24 J32.H27 J32.H30 J32.H33 J32.H36 J32.H39 J32.J1 J32.J4 J32.J5 J32.J8 J32.J11 J32.J14 J32.J17 J32.J20 J32.J23 J32.J26 J32.J29 J32.J32 J32.J35 J32.J38 J32.J40 J32.K2 J32.K3 J32.K6 J32.K9 J32.K12 J32.K15 J32.K18 J32.K21 J32.K24 J32.K27 J32.K30 J32.K33 J32.K36 J32.K39 J33.5(GND) J33.6(GND1) J33.7(GND2) J33.8(GND3) J33.9(GND4) J35.2 J35.3 J37.3 J38.2 JP9.3(PIN3) L4.1 L6.1 L7.1 L8.1 L11.1 L12.1 L15.1 L16.1 L45.2 L50.1 L51.1 L54.1 L55.1 L58.1 L59.1 L62.1 L63.1 MT1.1 MT2.1 MT3.1 MT4.1 MT5.1 MT6.1 Q1.2(E) Q2.2(E) Q3.2(E) Q4.2(E) Q5.2(E) Q6.2(E) Q7.2(E) Q8.2(E) Q9.2(E) Q10.2(E) Q11.2(E) Q12.2(E) Q13.2(E) Q14.2(E) Q15.2(E) Q16.2(E) Q17.2(E) Q18.2(E) Q19.2(E) Q20.2(E) Q21.2(E) Q22.2(E) Q23.2(E) Q25.1(S1) Q26.2(E) Q27.2(E) R2.2 R6.1 R7.2 R9.2 R15.1 R16.1 R20.2 R22.2 R23.2 R24.2 R25.2 R27.2 R28.2 R29.2 R30.2 R31.1 R50.1 R52.1 R72.1 R74.1 R93.1 R96.1 R118.1 R119.1 R138.2 R139.2 R142.2 R143.2 R146.2 R147.2 R150.2 R151.2 R153.2 R154.2 R155.2 R157.2 R160.2 R162.2 R163.2 R164.2 R165.2 R167.2 R168.2 R173.2 R174.2 R176.2 R177.2 R179.2 R180.2 R182.2 R183.2 R185.2 R186.2 R187.2 R188.2 R190.2 R192.2 R193.2 R194.2 R195.1 R214.2 R216.1 R222.1 R223.1 R224.1 R228.2 R232.2 R241.2 R243.2 R244.2 R248.2 R250.2 R252.1 R253.1 R254.1 R256.2 R258.1 R259.1 R260.1 R263.1 R264.2 R265.1 R266.1 R269.2 R270.1 R271.1 R272.1 R275.2 R276.1 R277.1 R278.1 R281.2 R282.1 R283.1 R284.1 R285.1 R288.2 R289.2 R290.2 R291.2 R292.2 R293.2 R294.2 R297.1 R298.1 R299.1 R300.1 R330.1 R331.1 R335.1 R336.1 R340.1 R341.1 R345.1 R346.1 SHIELD1.MT1 SHIELD1.MT2 SHIELD1.MT3 SHIELD2.MT1 SHIELD2.MT2 SHIELD2.MT3 SHIELD3.MT1 SHIELD3.MT2 SHIELD3.MT3 SHIELD4.MT1 SHIELD4.MT2 SHIELD4.MT3 SHIELD5.MT1 SHIELD5.MT2 SHIELD5.MT3 SHIELD5.MT4 SHIELD6.MT1 SHIELD6.MT2 SHIELD6.MT3 SHIELD6.MT4 SHIELD7.MT1 SHIELD7.MT2 SHIELD7.MT3 SHIELD7.MT4 SHIELD8.MT1 SHIELD8.MT2 SHIELD8.MT3 SHIELD8.MT4 SJP1.1(PIN1) SW1.1 T1.1(PRIMARY1_GND) T1.2(PRIMARY2_GND) T2.1(GND1) T2.3(GND2) T2.5(GND3) T3.1(GND1) T3.3(GND2) T3.5(GND3) T4.1(NC) T4.2(PRI/GND) T6.1(NC) T6.2(PRI/GND) T8.1(NC) T8.2(PRI/GND) T10.1(NC) T10.2(PRI/GND) T12.1(NC) T12.2(PRI/GND) T14.1(NC) T14.2(PRI/GND) T16.1(NC) T16.2(PRI/GND) T18.1(NC) T18.2(PRI/GND) T24.2(SECONDARY_CT) T24.4(PRIMARY) TP2.1(TP) U1.A1(VSST#A1) U1.A4(VSST#A4) U1.A5(RXAGND#A5) U1.A6(RXAGND#A6) U1.A9(RXAGND#A9) U1.A12(RXAGND#A12) U1.A15(RXAGND#A15) U1.A18(RXAGND#A18) U1.A19(VSSATXAB#A19) U1.A20(VSSATXAB#A20) U1.B2(VSST#B2) U1.B3(VSST#B3) U1.B4(VSST#B4) U1.B5(RXAGND#B5) U1.B6(RXAGND#B6) U1.B7(RXAGND#B7) U1.B8(RXAGND#B8) U1.B9(RXAGND#B9) U1.B10(RXAGND#B10) U1.B11(RXAGND#B11) U1.B12(RXAGND#B12) U1.B13(RXAGND#B13) U1.B14(RXAGND#B14) U1.B15(RXAGND#B15) U1.B16(RXAGND#B16) U1.B17(RXAGND#B17) U1.B18(RXAGND#B18) U1.B19(VSSATXAB#B19) U1.C2(VSST#C2) U1.C19(VSSATXAB#C19) U1.D1(VSST#D1) U1.D2(VSST#D2) U1.D19(VSSATXAB#D19) U1.D20(VSSATXAB#D20) U1.E2(VSST#E2) U1.E19(VSSATXAB#E19) U1.E20(VSSATXAB#E20) U1.F2(VSST#F2) U1.F12(DGND#F12) U1.F13(DGND#F13) U1.F16(VSSATXAB#F16) U1.F17(VSSATXAB#F17) U1.F18(VSSATXAB#F18) U1.F19(VSSATXAB#F19) U1.G1(VSST#G1) U1.G2(VSST#G2) U1.G12(DGND#G12) U1.G19(VSSATXAB#G19) U1.H2(VSST#H2) U1.H12(DGND#H12) U1.H19(VSSATXAB#H19) U1.H20(VSSATXAB#H20) U1.J2(VSST#J2) U1.J6(DGND#J6) U1.J7(DGND#J7) U1.J8(DGND#J8) U1.J9(DGND#J9) U1.J10(DGND#J10) U1.J11(DGND#J11) U1.J16(VSSCLK#J16) U1.J17(VSSCLK#J17) U1.J18(VSSCLK#J18) U1.J19(VSSCLK#J19) U1.J20(VSSCLK#J20) U1.K1(VSST#K1) U1.K3(VSST#K3) U1.K4(VSST#K4) U1.K20(VSSCLK#K20) U1.L1(VSST#L1) U1.L3(VSST#L3) U1.L4(VSST#L4) U1.L16(VSSCLK#L16) U1.L20(VSSCLK#L20) U1.M2(VSST#M2) U1.M6(DGND#M6) U1.M7(DGND#M7) U1.M8(DGND#M8) U1.M9(DGND#M9) U1.M10(DGND#M10) U1.M11(DGND#M11) U1.M16(VSSCLK#M16) U1.M18(VSSCLK#M18) U1.M19(VSSCLK#M19) U1.M20(VSSCLK#M20) U1.N2(VSST#N2) U1.N12(DGND#N12) U1.N19(VSSATXCD#N19) U1.N20(VSSATXCD#N20) U1.P1(VSST#P1) U1.P2(VSST#P2) U1.P12(DGND#P12) U1.P19(VSSATXCD#P19) U1.R2(VSST#R2) U1.R12(DGND#R12) U1.R13(DGND#R13) U1.R16(VSSATXCD#R16) U1.R17(VSSATXCD#R17) U1.R18(VSSATXCD#R18) U1.R19(VSSATXCD#R19) U1.T2(VSST#T2) U1.T19(VSSATXCD#T19) U1.T20(VSSATXCD#T20) U1.U1(VSST#U1) U1.U2(VSST#U2) U1.U19(VSSATXCD#U19) U1.U20(VSSATXCD#U20) U1.V2(VSST#V2) U1.V19(VSSATXCD#V19) U1.W2(VSST#W2) U1.W3(VSST#W3) U1.W4(VSST#W4) U1.W5(RXAGND#W5) U1.W6(RXAGND#W6) U1.W7(RXAGND#W7) U1.W8(RXAGND#W8) U1.W9(RXAGND#W9) U1.W10(RXAGND#W10) U1.W11(RXAGND#W11) U1.W12(RXAGND#W12) U1.W13(RXAGND#W13) U1.W14(RXAGND#W14) U1.W15(RXAGND#W15) U1.W16(RXAGND#W16) U1.W17(RXAGND#W17) U1.W18(RXAGND#W18) U1.W19(VSSATXCD#W19) U1.Y1(VSST#Y1) U1.Y4(VSST#Y4) U1.Y5(RXAGND#Y5) U1.Y6(RXAGND#Y6) U1.Y9(RXAGND#Y9) U1.Y12(RXAGND#Y12) U1.Y15(RXAGND#Y15) U1.Y18(RXAGND#Y18) U1.Y19(VSSATXCD#Y19) U1.Y20(VSSATXCD#Y20) U2.6(GND#6) U2.7(GND#7) U2.8(GND#8) U2.17(PWRPAD) U3.65(DAP) U4.2(GND) U5.1(GND#1) U5.5(GND#5) U5.10(AGND) U5.11(GND#11) U5.13(TEST) U5.15(GND#15) U5.25(GND#25) U5.35(GND#35) U5.47(GND#47) U5.51(GND#51) U6.11(GND) U6.21(PWRPAD) U7.11(GND) U7.21(PWRPAD) U8.5(GND) U9.11(GND) U9.21(PWRPAD) U10.7(GND) U11.7(GND) U11.8(1P6V) U11.21(PWRPAD) U12.2(GND) U13.6(VOS) U15.2(GND) U16.3(GND#3) U16.5(GND#5) U16.23(THERMPAD) U17.2(GND) U18.1(PGND1) U18.6(VSEL) U18.11(PGND2) U18.13(AGND) U19.2(GND) U20.8(GND#8) U20.18(GND#18) U20.21(THERMPAD) U21.2(GND) U22.8(GND#8) U22.18(GND#18) U22.21(THERMPAD) U23.8(GND#8) U23.18(GND#18) U23.21(THERMPAD) U24.2(GND) U25.8(GND#8) U25.18(GND#18) U25.21(THERMPAD) U26.2(GND) U27.8(GND#8) U27.18(GND#18) U27.21(THERMPAD) U28.2(GND) U29.8(GND#8) U29.18(GND#18) U29.21(THERMPAD) U30.2(GND) U31.3(A2) U31.4(VSS) U32.7(GND) U32.21(PWRPAD) U33.7(GND) Y1.3(GND) Y2.2 Y2.4
VDDA_1.0V: C76.1 C77.1 C365.1 C366.1 C429.1 FB26.3 PP13.1 U1.F15(VDDATXAB) U1.R15(VDDATXCD)
VDDA_1.8V: C78.1 C79.1 C80.1 C183.1 C192.1 C196.1 C203.1 C211.1 C215.1 C382.1 C383.1 C441.1 C442.1 C457.1 C458.1 FB31.3 L27.2 L28.1 L29.1 L31.1 L33.2 L34.1 L35.2 L36.1 L37.1 L39.1 L41.2 L42.1 PP19.1 U1.G18(VDDA18TXAB#G18) U1.H18(VDDA18TXAB#H18) U1.N18(VDDA18TXCD#N18) U1.P18(VDDA18TXCD#P18)
VDDA_SERDES_1.0V: C114.1 C115.1 C116.1 C410.1 C411.1 FB35.3 PP26.1 U1.D3(VDDA#D3) U1.D4(VDDA#D4) U1.U3(VDDA#U3) U1.U4(VDDA#U4)
VDDCLK_1.0V: C107.1 C108.1 C109.1 C359.1 C360.1 C431.1 FB24.3 PP11.1 U1.G16(VDDCLK#G16) U1.H16(VDDCLK#H16) U1.K17(VDDCLK#K17) U1.N16(VDDCLK#N16) U1.P16(VDDCLK#P16)
VDDE: C122.1 C123.1 C124.1 C125.1 C126.1 C325.1 C326.1 C459.1 C460.1 FB19.3 PP4.1 U1.F14(VDDETXAB#F14) U1.G14(VDDETXAB#G14) U1.H14(VDDETXAB#H14) U1.J14(VDDETXAB#J14) U1.M14(VDDETXCD#M14) U1.N14(VDDETXCD#N14) U1.P14(VDDETXCD#P14) U1.R14(VDDETXCD#R14)
VDDGPIO_1.8V: C42.1 C43.1 C44.1 C45.1 C46.1 C47.1 C48.1 C110.1 C356.1 C357.1 FB23.3 J9.57 J9.60 J9.63 JP2.2 JP3.2 JP4.2 JP5.2 JP6.2 JP7.2 JP8.2 PP10.1 R17.1 U1.D17(VDDGPIO18)
VDDL1_1.0V: C104.1 C105.1 C106.1 C348.1 C349.1 C464.1 C465.1 FB21.3 PP7.1 U1.G15(VDDL1TXAB#G15) U1.H15(VDDL1TXAB#H15) U1.N15(VDDL1TXCD#N15) U1.P15(VDDL1TXCD#P15)
VDDL2_1.0V: C101.1 C102.1 C103.1 C350.1 C351.1 C461.1 C462.1 FB22.3 PP9.1 U1.G17(VDDL2TXAB#G17) U1.H17(VDDL2TXAB#H17) U1.N17(VDDL2TXCD#N17) U1.P17(VDDL2TXCD#P17)
VDDPLL_1.0V: C91.1 C92.1 C369.1 C370.1 FB28.3 PP15.1 U1.K18(VDDPLL)
VDDPLL_1.8V: C93.1 C94.1 C367.1 C368.1 FB27.3 PP14.1 U1.L18(VDDAPLL18)
VDDR_SERDES_1.5V: C111.1 C112.1 C113.1 C416.1 C417.1 FB36.3 PP27.1 U1.F3(VDDR#F3) U1.F4(VDDR#F4) U1.R3(VDDR#R3) U1.R4(VDDR#R4)
VDDT_SERDES_1.0V: C117.1 C118.1 C119.1 C402.1 C403.1 FB34.3 PP24.1 U1.H3(VDDT#H3) U1.H4(VDDT#H4) U1.N3(VDDT#N3) U1.N4(VDDT#N4)
VDDTX_1.0V: C99.1 C100.1 C376.1 C379.1 FB30.3 PP18.1 U1.J15(VDDTX)
VDDTX_1.8V: C97.1 C98.1 C375.1 C378.1 FB29.1 PP17.1 U1.K16(VDDTX18)
VDDVCO_1.8V: C95.1 C96.1 C363.1 C364.1 FB25.3 PP12.1 U1.L17(VDDAVCO18#L17) U1.M17(VDDAVCO18#M17)
VEE: C61.1 C62.1 C63.1 C64.1 C65.1 C316.1 C318.1 C430.1 C463.1 FB18.3 PP2.1 U1.D18(VEETXAB#D18) U1.E17(VEETXAB#E17) U1.E18(VEETXAB#E18) U1.T17(VEETXCD#T17) U1.T18(VEETXCD#T18) U1.U17(VEETXCD#U17)
3P3V_FMC: J32.C39 J32.D36 J32.D38 J32.D40 PP30.1
3P3VAUX: C422.2 J32.D32 J37.4 PP31.1 U31.8(VCC)
A_IN1: J14.1(CENTER) R50.2 R54.1
A_IN2: J15.1(CENTER) R330.2 R332.1
ADC_ALT_SYNC_N: J32.H32 U1.N10(SYNCBINM1)
ADC_ALT_SYNC_P: J32.H31 U1.N11(SYNCBINP1)
ADC_SYNC_N: J32.G13 U1.H10(SYNCBINM0)
ADC_SYNC_P: J32.G12 U1.H11(SYNCBINP0)
AIN1: C132.2 L7.2 T4.3(PRI DOT)
AIN1M: C136.1 U1.A16(RXADSA1M)
AIN1P: C131.1 U1.A17(RXADSA1P)
AIN2: C471.2 L51.2 T6.3(PRI DOT)
AIN2M: C475.1 U1.A13(RXADSA2M)
AIN2P: C474.1 U1.A14(RXADSA2P)
ALARM_TX1: J7.1 Q3.1(B)
ALARM_TX2: J7.4 Q4.1(B)
ALARMTX1: J7.2 U1.C17(TXALARM1)
ALARMTX2: J7.5 U1.V17(TXALARM2)
B_IN1: J16.1(CENTER) R72.2 R76.1
B_IN2: J17.1(CENTER) R335.2 R337.1
BIN1: C137.2 L8.2 T8.3(PRI DOT)
BIN1M: C145.1 U1.A10(RXBDSA1M)
BIN1P: C144.1 U1.A11(RXBDSA1P)
BIN2: C479.2 L55.2 T10.3(PRI DOT)
BIN2M: C483.1 U1.A7(RXBDSA2M)
BIN2P: C482.1 U1.A8(RXBDSA2P)
BOOT: R235.2 U16.4(BOOT)
C_IN1: J18.1(CENTER) R94.1 R96.2
C_IN2: J19.1(CENTER) R340.2 R342.1
CAR_SYSREF_M: R158.1 R162.1 U3.4(SDCLKOUT1N)
CAR_SYSREF_P: R156.1 R163.1 U3.3(SDCLKOUT1P)
CAR_SYSREFM: J32.G10 R158.2
CAR_SYSREFP: J32.G9 R156.2
